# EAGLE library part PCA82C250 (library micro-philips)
CAN CONTROLLER INTERFACE
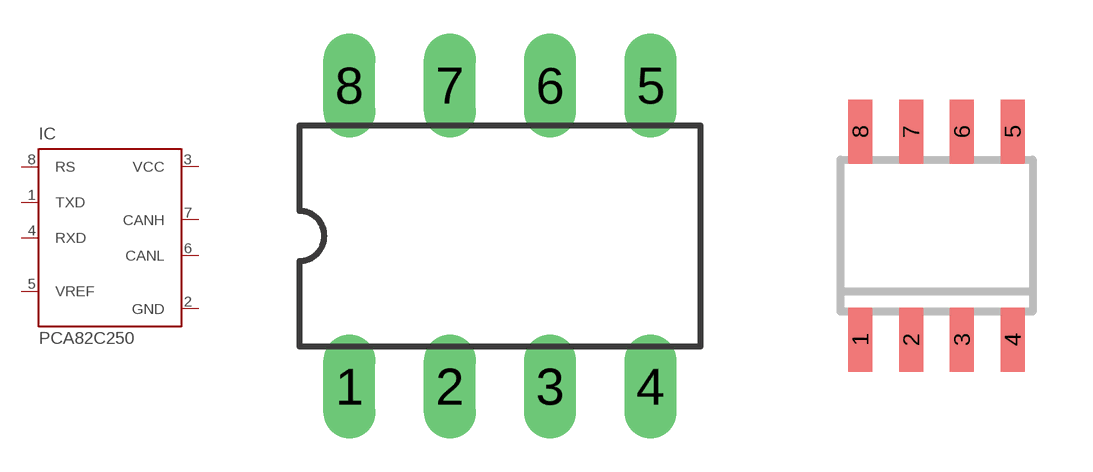
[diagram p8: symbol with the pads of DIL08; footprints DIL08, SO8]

Designator prefix IC

## PCA82C250 (OC_FARNELL: 3692358; OC_NEWARK: unknown)  [DIL08]
1  TXD  in
2  GND  pwr
3  VCC  pwr
4  RXD  out
5  VREF  out
6  CANL
7  CANH
8  RS  in

## PCA82C250T (OC_FARNELL: 1085275; OC_NEWARK: unknown)  [SO8]
Pads as for DIL08

## Footprint DIL08 (pad centres in mm)
Dual In Line
drill 0.813 long: 1 -3.81,-3.81; 2 -1.27,-3.81; 3 1.27,-3.81; 4 3.81,-3.81; 5 3.81,3.81; 6 1.27,3.81; 7 -1.27,3.81; 8 -3.81,3.81

## Footprint SO8 (pad centres in mm)
SO8: plastic small outline package; 8 leads; body width 3.9 mm Source: http://www.nxp.com/documents/data_sheet/PCA82C250.pdf
smd 0.6 x 1.6: 1 -1.905,-2.6; 2 -0.635,-2.6; 3 0.635,-2.6; 4 1.905,-2.6; 5 1.905,2.6; 6 0.635,2.6; 7 -0.635,2.6; 8 -1.905,2.6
